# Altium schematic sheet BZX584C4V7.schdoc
size 127 x 101 mm
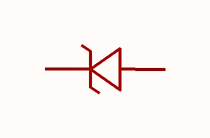
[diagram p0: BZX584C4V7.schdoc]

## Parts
D?  bzx584c4v7  [SOD-523_L1.2-W0.8-LS1.6-RD-1]  (value not drawn)

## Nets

Not connected (* = marked no-connect by the designer): D? 1(K) 2(A)

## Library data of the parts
D? = bzx584c4v7: 二极管配置:1个独立式;稳压值(标称值):4.7V;稳压值(范围):4.4V~5V;耗散功率(Pd):150mW;; Manufacturer: CJ(江苏长电/长晶); AddInBom: yes; ModelId: d10bb3db7b4b41808fe672faecd39ab5; ModelTransform: 62.992,31.496,0,0,0,0,0,0,0; Diode Configuration: 1个独立式; Zener Voltage(Nom): 4.7V; Reverse Leakage Current (Ir): 3uA@1V; Pd - Power Dissipation: 150mW; Impedance(Zzt): 80Ω; Impedance(Zzk): 500Ω; Operating Junction Temperature Range: -55℃~+150℃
